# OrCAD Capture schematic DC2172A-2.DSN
size Custom; title: HIGH EFFICIENCY, HIGH VIN, 400mA; rev: 2; company: TM; note: STEP-DOWN REGULATOR
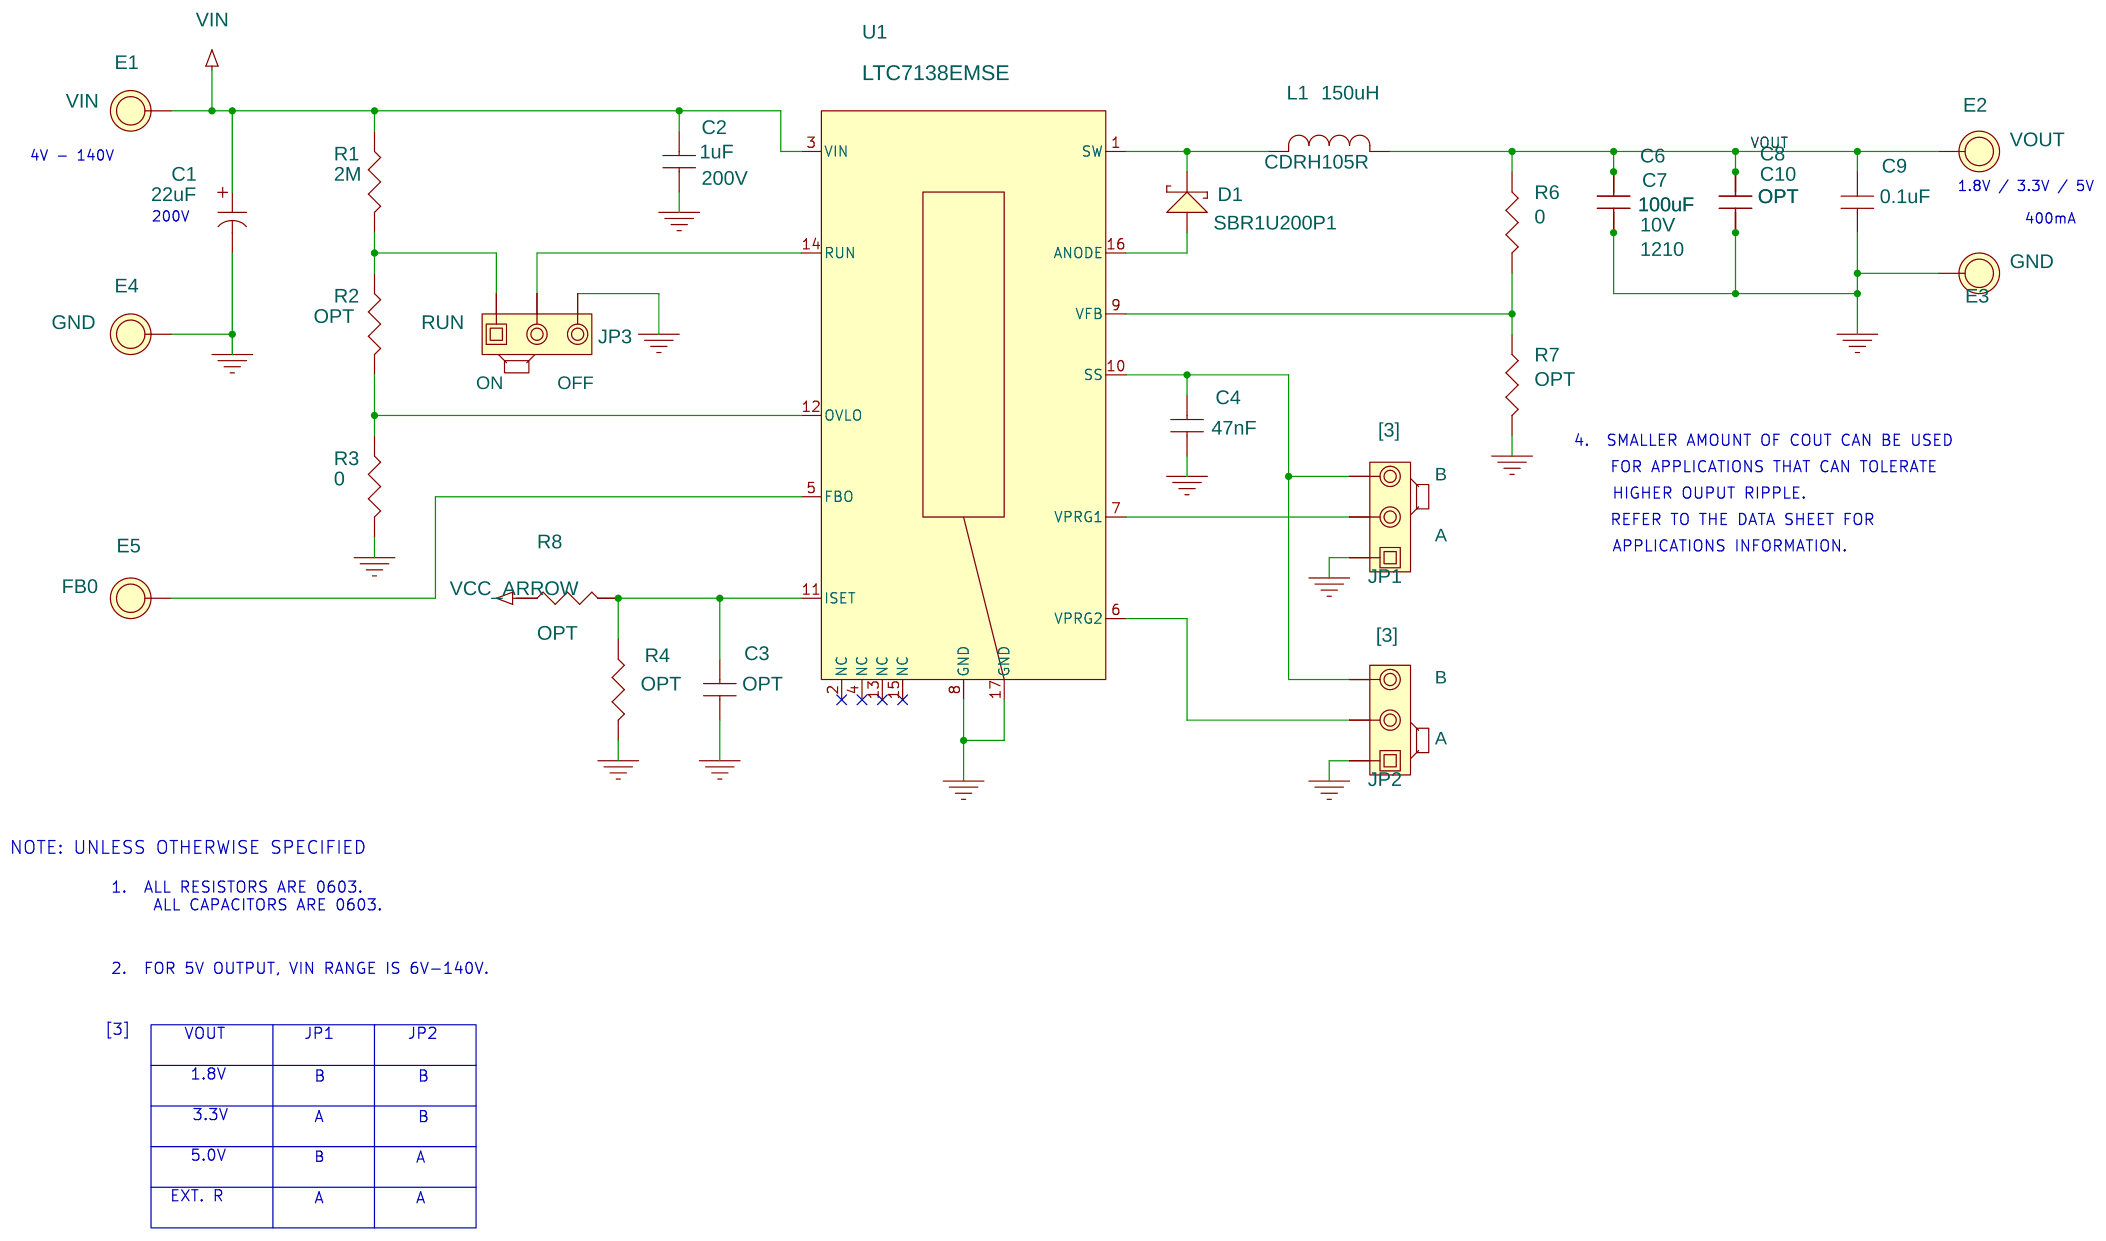
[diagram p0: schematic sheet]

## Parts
C1  22uF  [CAP\NIP_CEM-CON\13X13]
C2  1uF  [CAP2220]
C3  OPT  [0603]
C4  47nF  [0603]
C6  100uF  [1210]
C7  100uF  [1210]
C8  OPT  [1210]
C9  0.1uF  [0603]
C10  OPT  [1210]
D1  SBR1U200P1  [POWERDI123-KS]
E1  3A  [MM/2501]
E2  3A  [MM/2501]
E3  3A  [MM/2501]
E4  3A  [MM/2501]
E5  3A  [MM/2501]
JP1  3 Pins 2mm Ctrs.  [JP3X1/079]
JP2  3 Pins 2mm Ctrs.  [JP3X1/079]
JP3  3 Pins 2mm Ctrs.  [JP3X1/079]
L1  150uH  [L-CDRH105R]
R1  2M  [0603]
R2  OPT  [0603]
R3  0  [0603]
R4  OPT  [0603]
R6  0  [0603]
R7  OPT  [0603]
R8  OPT  [0603]
U1  LTC7138EMSE  [MSE-16L(12)]
XJP1  2mm Ctrs.
XJP2  2mm Ctrs.
XJP3  2mm Ctrs.

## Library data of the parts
C1 = CAP: CAP, 22uF 200V ELEC; Part Number: NIPPON CHEMI-CON, EMVE201ARA220MKG5S
C2 = CAP2220: CAP, 2220 1uF 10% 200V X7R; 1ST PART FIELD: 200V; Part Number: KEMET C2220X105K2RACTU
C3 = CAP0603: CAP 0603 OPTION; Part Number: OPTION
C4 = CAP0603: CAP, 0603 47nF 10% 25V X7R; Part Number: AVX 06033C473KAT2A
C6 C7 = CAP1210: CAP 1210 100uF 20% 10V X7R; 1ST PART FIELD: 10V; Part Number: TAIYO YUDEN LMK325ABJ107MMH-T
C8 C10 = CAP1210: CAP 1210 OPTION; 1ST PART FIELD: 10V; Part Number: OPTION
C9 = CAP0603: CAP 0603 0.1uF 10% 25V X7R; Part Number: AVX 06033C104KAT2A
D1 = DIODE-DFLS1100-POWERDI123_0: DIODE, SBR1U200P1; Part Number: DIODES, SBR1U200P1-7
E1 = E_4: TURRET; INPUT: VIN; Part Number: MILL-MAX 2501-2-00-80-00-00-07-0; STATUS: 1.6V, 1.8V, 2.0V OR 2.5V @ 15A
E2 = E_4: TURRET; INPUT: VOUT; Part Number: MILL-MAX 2501-2-00-80-00-00-07-0; STATUS: 1.6V, 1.8V, 2.0V OR 2.5V @ 15A
E3 E4 = E_4: TURRET; INPUT: GND; Part Number: MILL-MAX 2501-2-00-80-00-00-07-0; STATUS: 1.6V, 1.8V, 2.0V OR 2.5V @ 15A
E5 = E_4: TURRET; INPUT: FB0; Part Number: MILL-MAX 2501-2-00-80-00-00-07-0; STATUS: 1.6V, 1.8V, 2.0V OR 2.5V @ 15A
JP1 JP2 = Samtec_TMM-103-02-L-S: HEADER, 2mm, 3PIN; 11th Part Field: B; 12th Part Field: [3]; 9th Part Field: A; Part Number: SULLINS, NRPN031PAEN-RC
JP3 = Samtec_TMM-103-02-L-S: HEADER, 2mm, 3PIN; 11th Part Field: OFF; 12th Part Field: RUN; 9th Part Field: ON; Part Number: SULLINS, NRPN031PAEN-RC
L1 = IND-TDK-VLF: IND 150uH; 5TH PART FIELD: CDRH105R; Part Number: SUMIDA CDRH105RNP-151NC
R1 = AAC-0603: RES 0603 2M OHMS 5% 1/10W; Part Number: VISHAY CRCW06032M00JNEA
R2 R4 R7 R8 = AAC-0603: RES, 0603 OPTION; Part Number: OPTION
R3 R6 = AAC-0603: RES, 0603 0 OHM JUMPER; Part Number: VISHAY CRCW06030000Z0ED
U1 = LTC3630EMSE_4: IC LTC7138EMSE; Part Number: LINEAR TECH LTC7138EMSE
XJP1-XJP3 = Samtec_2SN-BK-G: SHUNT, 2mm; Part Number: SAMTEC 2SN-BK-G

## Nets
GND: C1.2 C2.2 C3.2 C4.2 C6.2 C7.2 C8.2 C9.2 C10.2 E3.1(A) E4.1(A) JP1.1 JP2.1 JP3.3 R3.2 R4.2 R7.2 U1.8(GND) U1.17(GND)
VIN: C1.1 C2.1 E1.1(A) R1.1 R8.1 U1.3(VIN)
VOUT: C6.1 C7.1 C8.1 C9.1 C10.1 E2.1(A) L1.2 R6.1
N917668: JP3.1 R1.2 R2.1
N917672: JP3.2 U1.14(RUN)
N917786: JP1.2 U1.7(VPRG1)
N917844: R2.2 R3.1 U1.12(OVLO)
N917972: E5.1(A) U1.5(FBO)
N918024: C3.1 R4.1 R8.2 U1.11(ISET)
N918032: D1.2 U1.16(ANODE)
N918076: C4.1 JP1.3 JP2.3 U1.10(SS)
N918094: JP2.2 U1.6(VPRG2)
N918228: R6.2 R7.1 U1.9(VFB)
N918434: D1.1 L1.1 U1.1(SW)

Not connected (* = marked no-connect by the designer): U1 2(NC)* 4(NC)* 13(NC)* 15(NC)*

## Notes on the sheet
- 4V - 140V
- 1.8V / 3.3V / 5V
- 200V
- 400mA
- 4.  SMALLER AMOUNT OF COUT CAN BE USED
- FOR APPLICATIONS THAT CAN TOLERATE
- HIGHER OUPUT RIPPLE.
- REFER TO THE DATA SHEET FOR
- APPLICATIONS INFORMATION.
- NOTE: UNLESS OTHERWISE SPECIFIED
- 1.  ALL RESISTORS ARE 0603.
       ALL CAPACITORS ARE 0603.
- 2.  FOR 5V OUTPUT, VIN RANGE IS 6V-140V.
- [3]
- VOUT
- JP1
- JP2
- 1.8V
- B
- B
- 3.3V
- A
- B
- 5.0V
- B
- A
- EXT. R
- A
- A
